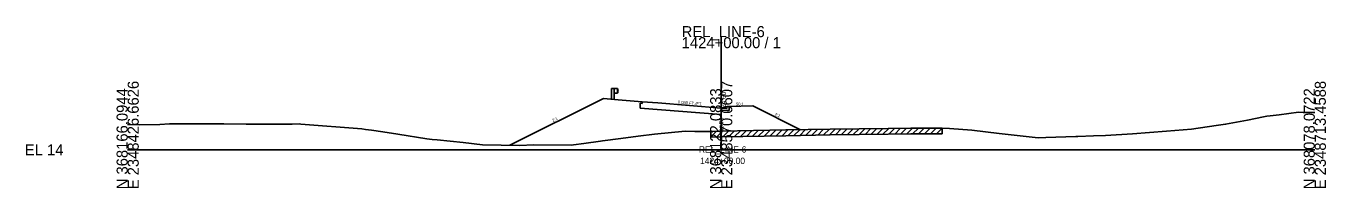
# Model space of a CAD drawing. Extents: x -26 to 403, y -10 to 6565.
# Drawn here: x -25.7 to 302.8, y 4490.3 to 4531.4 of the extents above; entities that cross this region are included whole.
import ezdxf

# ---------------------------------------------------------------- set-up
doc = ezdxf.new("R2010")
doc.units = 0
for name, color, linetype in [('RD_GPK_XS_Cell', 7, 'Continuous'), ('RD_XS_Base', 7, 'Continuous'), ('RD_XS_CurbBase', 7, 'Continuous'), ('RD_XS_CurbFront', 7, 'Continuous'), ('RD_XS_CurbTop', 7, 'Continuous'), ('RD_XS_EarthShd', 7, 'Continuous'), ('RD_XS_ExGround', 7, 'Continuous'), ('RD_XS_ExPaveRet', 7, 'Continuous'), ('RD_XS_GR', 7, 'Continuous'), ('RD_XS_Pave', 7, 'Continuous'), ('RD_XS_PaveShd', 7, 'Continuous'), ('RD_XS_TieSlope', 7, 'Continuous'), ('RD_XS_TX_Elev_EX', 7, 'Continuous'), ('RD_XS_TX_Elev_PR', 7, 'Continuous'), ('RD_XS_TX_Slope', 7, 'Continuous'), ('RD_XS_TX_Station', 7, 'Continuous'), ('RD_XS_TX_TOC', 7, 'Continuous')]:
    doc.layers.add(name, color=color, linetype=linetype)

msp = doc.modelspace()

# ---------------------------------------------------------------- linework, layer by layer
at = {"layer": 'RD_GPK_XS_Cell'}
for p, q in [((150, 4500), (150, 4528.56)), ((0, 4500), (150, 4500)), ((150, 4500), (300, 4500))]:
    msp.add_line(p, q, dxfattribs=at)
at = {"layer": 'RD_XS_Base'}
for p, q in [((130, 4511.75), (129.5, 4511.79)), ((129.5, 4511.79), (129.5, 4510.6)), ((130, 4512.2), (130, 4511.75)), ((150, 4508.96), (129.5, 4510.6))]:
    msp.add_line(p, q, dxfattribs=at)
at = {"layer": 'RD_XS_CurbBase'}
for p, q in [((152, 4511), (152, 4510)), ((151.5, 4510), (150, 4510.08)), ((150, 4508.96), (150, 4510.08)), ((152, 4510), (151.5, 4510))]:
    msp.add_line(p, q, dxfattribs=at)
at = {"layer": 'RD_XS_CurbFront'}
msp.add_line((150, 4510.08), (150, 4510.58), dxfattribs=at)
at = {"layer": 'RD_XS_CurbTop'}
for p, q in [((151.42, 4510.5), (151.5, 4511)), ((151.5, 4511), (152, 4511)), ((150, 4510.6), (150, 4510.58)), ((150, 4510.58), (151.42, 4510.5))]:
    msp.add_line(p, q, dxfattribs=at)
at = {"layer": 'RD_XS_EarthShd'}
for p, q in [((120.25, 4512.98), (96.6, 4501.16)), ((124, 4512.68), (120.25, 4512.98)), ((130, 4512.2), (124, 4512.68)), ((152, 4511), (158, 4511.12))]:
    msp.add_line(p, q, dxfattribs=at)
at = {"layer": 'RD_XS_ExGround'}
msp.add_lwpolyline([(0, 4506.42), (2.97, 4506.35), (8.1, 4506.46), (10.54, 4506.55), (12.77, 4506.55), (20.89, 4506.55), (24.34, 4506.56), (29.98, 4506.52), (35.85, 4506.51), (37.22, 4506.49), (38.04, 4506.51), (41.56, 4506.54), (43.39, 4506.57), (43.75, 4506.51), (59.16, 4505.29), (60.13, 4505.16), (61.59, 4504.96), (64.45, 4504.55), (68.27, 4503.94), (75.64, 4502.83), (76.95, 4502.64), (78.18, 4502.5), (84.82, 4501.9), (89.71, 4501.24), (99.14, 4501.13), (102.56, 4501.3), (112.24, 4501.2), (112.66, 4501.25), (115.27, 4501.62), (119.47, 4502.23), (120.04, 4502.28), (124.67, 4502.84), (129.05, 4503.49), (133.15, 4503.96), (140.93, 4504.71), (143.33, 4504.68), (147.38, 4504.68), (150, 4504.73), (166.33, 4505.03), (177.52, 4505.25), (192.18, 4505.43), (197.94, 4505.47), (205.85, 4505.49), (207.66, 4505.37), (213.31, 4504.96), (220.25, 4504.1), (230.12, 4503.08), (232.06, 4503.13), (239.6, 4503.4), (240.15, 4503.42), (244.05, 4503.51), (247.08, 4503.61), (253.97, 4504.08), (262.55, 4504.74), (268.83, 4505.2), (275.06, 4506.17), (277.48, 4506.5), (280.23, 4507.01), (282.99, 4507.49), (287.07, 4508.34), (287.87, 4508.5), (288.72, 4508.61), (291.03, 4508.85), (295.88, 4509.52), (297.04, 4509.43), (300, 4509.43)], dxfattribs=at)
at = {"layer": 'RD_XS_ExPaveRet'}
for p, q in [((147.38, 4503.25), (148.84, 4504.71)), ((147.38, 4503.25), (147.38, 4504.68)), ((148.88, 4503.27), (150.34, 4504.74)), ((150.38, 4503.3), (151.84, 4504.76)), ((151.88, 4503.33), (153.34, 4504.79)), ((153.38, 4503.36), (154.84, 4504.82)), ((154.88, 4503.38), (156.34, 4504.85)), ((156.38, 4503.41), (157.84, 4504.87)), ((157.88, 4503.44), (159.34, 4504.9)), ((159.38, 4503.46), (160.84, 4504.93)), ((160.88, 4503.49), (162.34, 4504.96)), ((162.38, 4503.52), (163.84, 4504.98)), ((163.88, 4503.55), (165.34, 4505.01)), ((165.38, 4503.57), (166.84, 4505.04)), ((166.88, 4503.6), (168.34, 4505.07)), ((168.38, 4503.63), (169.84, 4505.1)), ((169.88, 4503.66), (171.34, 4505.13)), ((171.38, 4503.69), (172.84, 4505.16)), ((172.88, 4503.72), (174.34, 4505.19)), ((174.38, 4503.75), (175.84, 4505.22)), ((175.88, 4503.78), (177.34, 4505.25)), ((177.38, 4503.81), (178.83, 4505.27)), ((178.88, 4503.83), (180.33, 4505.29)), ((180.38, 4503.85), (181.83, 4505.3)), ((181.88, 4503.87), (183.33, 4505.32)), ((183.38, 4503.88), (184.83, 4505.34)), ((184.88, 4503.9), (186.33, 4505.36)), ((186.38, 4503.92), (187.83, 4505.38)), ((187.88, 4503.94), (189.33, 4505.39)), ((189.38, 4503.96), (190.83, 4505.41)), ((190.88, 4503.97), (192.33, 4505.43)), ((192.38, 4503.99), (193.82, 4505.44)), ((193.88, 4504), (195.32, 4505.45)), ((195.38, 4504.02), (196.82, 4505.46)), ((196.88, 4504.03), (198.32, 4505.47)), ((198.38, 4504.04), (199.82, 4505.48)), ((199.88, 4504.04), (201.32, 4505.48)), ((201.38, 4504.05), (202.82, 4505.49)), ((202.88, 4504.05), (204.32, 4505.49)), ((204.38, 4504.05), (205.82, 4505.49)), ((205.85, 4505.49), (205.85, 4504.06)), ((147.38, 4503.25), (150, 4503.29)), ((150, 4503.29), (166.33, 4503.59)), ((166.33, 4503.59), (177.52, 4503.81)), ((177.52, 4503.81), (192.18, 4503.99)), ((192.18, 4503.99), (197.94, 4504.04)), ((197.94, 4504.04), (205.85, 4504.06))]:
    msp.add_line(p, q, dxfattribs=at)
at = {"layer": 'RD_XS_GR'}
for p, q in [((122.92, 4515.51), (122.25, 4515.51)), ((122.25, 4515.51), (122.25, 4512.82)), ((123.83, 4515.51), (122.92, 4515.51)), ((122.92, 4515.51), (122.92, 4512.77)), ((123.83, 4514.34), (122.92, 4514.34)), ((123.83, 4514.34), (123.83, 4515.51)), ((123.83, 4515.44), (124, 4515.24)), ((124, 4515.19), (123.83, 4514.99)), ((124, 4514.67), (123.83, 4514.87)), ((123.83, 4514.42), (124, 4514.62)), ((124, 4515.24), (124, 4515.19)), ((124, 4514.62), (124, 4514.67))]:
    msp.add_line(p, q, dxfattribs=at)
at = {"layer": 'RD_XS_Pave'}
msp.add_line((134, 4511.88), (150, 4510.6), dxfattribs=at)
at = {"layer": 'RD_XS_PaveShd'}
msp.add_line((134, 4511.88), (130, 4512.2), dxfattribs=at)
at = {"layer": 'RD_XS_TieSlope'}
msp.add_line((158, 4511.12), (170.03, 4505.1), dxfattribs=at)

# ---------------------------------------------------------------- texts
at = {"layer": 'RD_GPK_XS_Cell'}
for s, p in [('REL_LINE-6', (140, 4528.56)), ('1424+00.00 / 1', (140, 4525.76)), ('EL 14', (-26, 4498.6))]:
    msp.add_text(s, height=2.8, dxfattribs=at).set_placement(p)
for s, p in [('N 368166.0944', (0, 4490)), ('E 2348426.6626', (2.8, 4490)), ('N 368122.0833', (150, 4490)), ('E 2348570.0607', (152.8, 4490)), ('N 368078.0722', (300, 4490)), ('E 2348713.4588', (302.8, 4490))]:
    msp.add_text(s, height=2.8, rotation=90, dxfattribs=at).set_placement(p)
at = {"layer": 'RD_XS_TX_Elev_EX'}
msp.add_text('18.73', height=1, rotation=90, dxfattribs=at).set_placement((150.5, 4504.73))
at = {"layer": 'RD_XS_TX_Elev_PR'}
msp.add_text('24.60', height=1.2, rotation=90, dxfattribs=at).set_placement((151.2, 4510.6))
at = {"layer": 'RD_XS_TX_Slope'}
for s, rotation, p in [('0.080 FT./FT.', 355.4291, (139, 4511.73)), ('50:1', 1.1458, (153.73, 4511.19)), ('2:1', 26.5651, (107.48, 4507.05)), ('2:1', 333.4349, (163.41, 4508.78))]:
    msp.add_text(s, height=0.75, rotation=rotation, dxfattribs=at).set_placement(p)
at = {"layer": 'RD_XS_TX_Station'}
for s, p in [('REL_LINE-6', (144.35, 4499.31)), ('1424+00.00', (144.66, 4496.41))]:
    msp.add_text(s, height=1.6, dxfattribs=at).set_placement(p)
at = {"layer": 'RD_XS_TX_TOC'}
msp.add_text('TOCRT', height=0.05, dxfattribs=at).set_placement((151.22, 4510.95))

doc.saveas('drawing.dxf')
